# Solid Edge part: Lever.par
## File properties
Author: wojci
Template: ISO Metric Part.par
Last saved by: wojci
Revision: 29
Application: Solid Edge
Username: wojci
Accuracy: 0.990
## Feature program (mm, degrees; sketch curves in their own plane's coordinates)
sketch for "unnamed Protrusion 1" plane through (0, 0, 0) normal (0, -1, 0) x-axis (1, 0, 0)
  arc centre (32.0198, -7.9834) radius 5 from (27.2135, -9.3616) to (30.8101, -12.8349) ccw
  arc centre (32.3827, -6.5278) radius 6.5002 from (30.8101, -12.8349) to (34.1079, -0.2607) ccw
  line (10.286, 6.1805) -> (34.1079, -0.2607)
  line (-35.9088, 21.3204) -> (2.9031, 11.6435)
  arc centre (-37.1184, 16.4689) radius 5 from (-35.9088, 21.3204) to (-41.9699, 17.6786) ccw
  line (-47.5341, -4.6382) -> (-41.9699, 17.6786)
  line (-47.5341, -4.6382) -> (-31.6385, 4.1728)
  line (-30.2825, 9.6115) -> (-31.6385, 4.1728)
  line (-30.2825, 9.6115) -> (-6.0251, 3.5635)
  line (-1.6935, -6.7921) -> (27.2135, -9.3616)
extrude "unnamed Protrusion 1" add finite 27.5 along -normal
sketch for "ExtrudedCutout_1" plane through (-2.2401, 27.5, 3.5583) normal (0, 1, 0) x-axis (-0.996073, 0, 0.088541)
extrude "ExtrudedCutout_1" cut finite 8 along -normal
sketch for "unnamed Cutout 1" plane through (32.0198, 0, -7.9834) normal (0.241922, 0, 0.970296) x-axis (0.970296, 0, -0.241922)
  line (-7.5, 12.7) -> (-7.5, 5.4)
  line (7.5, 5.4) -> (-7.5, 5.4)
  line (7.5, 5.4) -> (7.5, 12.7)
  line (7.5, 12.7) -> (-7.5, 12.7)
extrude "unnamed Cutout 1" cut through along +normal
sketch for "ExtrudedProtrusion_3" plane through (-2.2401, 0, 3.5583) normal (0, -1, 0) x-axis (0.996073, 0, -0.088541)
  circle centre (2.5464, -3.346) radius 12
extrude "ExtrudedProtrusion_3" add finite 12.5 along -normal
sketch for "ExtrudedCutout_4" plane through (-2.2401, 0, 3.5583) normal (0, -1, 0) x-axis (0.970296, 0, -0.241922)
  line (4.0847, -14.8646) -> (-41.9656, -18.9106)
  line (-41.9656, -18.9106) -> (-41.9656, 9.0894)
  line (-41.9656, 9.0894) -> (3.0344, 9.0894)
  arc centre (3.0344, -2.9106) radius 12 from (3.0344, 9.0894) to (4.0847, -14.8646) ccw
extrude "ExtrudedCutout_4" cut finite 12.5 along -normal
sketch for "ExtrudedCutout_5" plane through (12.5099, 0, -0.3117) normal (0, -1, 0) x-axis (0.996073, 0, -0.088541)
  line (-2.79, 6.2698) -> (-2.79, -7.8641)
  arc centre (-12.4883, -0.7971) radius 12 from (-2.79, 6.2698) to (-2.79, -7.8641) ccw
extrude "ExtrudedCutout_5" cut finite 2.5 along -normal
sketch for "ExtrudedCutout_6" plane through (-14.7469, 27.5, 5.718) normal (0, 1, 0) x-axis (-0.970296, 0, 0.241922)
  line (-14.1589, -1.5234) -> (-8.984, 0.0195)
  arc centre (-15.6922, -1.9805) radius 7 from (-8.984, 0.0195) to (-15.6922, -8.9805) cw
  line (-15.6922, -3.5805) -> (-15.6922, -8.9805)
  dimension (linear) = 14.1589
  dimension (linear) = 15.6922
extrude "ExtrudedCutout_6" cut finite 15 along -normal
sketch for "ExtrudedProtrusion_4" plane through (-14.75, 27.5, 5.7186) normal (0, 1, 0) x-axis (-0.970296, 0, 0.241922)
  arc centre (-15.6953, -1.9804) radius 12 from (-15.6953, 10.0196) to (-26.4561, -7.2914) ccw
  arc centre (-15.6953, -1.9804) radius 12 from (-26.4561, -7.2914) to (-3.8632, 0.0196) ccw
  arc centre (-15.6953, -1.9804) radius 12 from (-15.6953, 10.0196) to (-3.8632, 0.0196) cw
extrude "ExtrudedProtrusion_4" add finite 25 along +normal
sketch for "ExtrudedCutout_7" plane through (-1.8397, 27.5, -3.5559) normal (0, -1, 0) x-axis (0.996073, 0, -0.088541)
  line (-9.8613, 7.5154) -> (-4.7993, 6.7209)
  line (-4.7993, 6.7209) -> (0.0738, 4.3942)
  arc centre (1.5177, 3.7049) radius 1.6 from (1.2696, 2.1242) to (0.0738, 4.3942) ccw
  line (1.2696, 2.1242) -> (0.4322, -3.2105)
  line (0.4322, -3.2105) -> (11.3247, -3.2105)
  arc centre (1.5177, 3.7049) radius 12 from (-9.8613, 7.5154) to (11.3247, -3.2105) ccw
extrude "ExtrudedCutout_7" cut finite 1 along -normal  FiniteDepth2 = 17 mm
sketch for "Hole_3" plane through (0, 52.5, 0) normal (0, 1, 0) x-axis (-1, 0, 0)
  hole centre (0, 0) bore radius 1.7
hole "Hole_3" diameter 3.4 through
chamfer "Chamfer_4" setback 3
chamfer "Chamfer_6" setback 1.5
chamfer "Chamfer_7" setback 2
sketch for "Hole_4" plane through (24.6721, 0, -5.1821) normal (0, -1, 0) x-axis (0.996073, 0, -0.088541)
  hole centre (7.5668, -2.1397) bore radius 1.2295
hole "Hole_4" nominal diameter 3 through  ThreadDepth = 2 mm
fillet "Round_8" radius 3.5
fillet "Round_9" radius 10
chamfer "Chamfer_11" setback 2
chamfer "Chamfer_12" setback 3.5643
fillet "Round_10" radius 1
chamfer "Chamfer_13" setback 1.5
fillet "Round_11" radius 1.5
sketch for "unnamed Cutout 2" plane through (-21.52, 12.5, 11.0446) normal (0, -1, 0) x-axis (0.970296, 0, -0.241922)
  line (-19.4473, -19.6454) -> (-19.4473, -2.5104)
  arc centre (-10.4473, -2.5104) radius 9 from (-19.4473, -2.5104) to (-10.4473, 6.4896) cw
  line (-10.4473, 6.4896) -> (-21.4473, 6.4896)
  line (-21.4473, -21.5104) -> (-21.4473, 6.4896)
  line (-19.4473, -19.6454) -> (-21.4473, -21.5104)
extrude "unnamed Cutout 2" cut through along -normal
fillet "Round_15" radius 3.5
fillet "Round_16" radius 3
fillet "Round_17" radius 1.5
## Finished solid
Body 1: solid body, 52 faces, 142 edges, 88 vertices.
  Faces by surface: plane 25, cylinder 20, cone 5, torus 2
  Edges by curve: line 72, circle 52, intersection 17, ellipse 1
Bounding box of the edges (mm; curved faces can reach further): 82.182 x 52.500 x 33.164, from (-43.2989, 0, -13.028) to (38.8829, 52.5, 20.1362).
Cylindrical faces by radius (mm): R1 x3, R1.2295 x3, R1.5 x3, R1.7 x1, R3 x1, R3.5 x2, R5 x2, R6.5002 x2, R9 x1, R10 x1, R12 x1
Conical faces (half-angle, radius in mm at the cone's reference point): 45 deg R10 x1, 45 deg R10.5 x1, 45 deg R12 x2, 45 deg R15 x1
Toroidal faces (ring radius, tube radius in mm): R2.7 r1 x2
Planar faces by outward normal: +y 5, -y 5, oblique 15
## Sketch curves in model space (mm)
line (32.0198, 0, -7.9834) -> (32.0198, 19.5, -7.9834)
line (39.297, 12.7, -9.7978) -> (24.7425, 12.7, -6.169)
line (24.7425, 12.7, -6.169) -> (24.7425, 5.4, -6.169)
line (39.297, 5.4, -9.7978) -> (24.7425, 5.4, -6.169)
line (39.297, 5.4, -9.7978) -> (39.297, 12.7, -9.7978)
line (2.9031, 0, 11.6435) -> (0, 0, 0)
line (-43.6633, 0, 10.8865) -> (-47.5341, 0, -4.6382)
line (-36.8712, 0, 9.193) -> (-43.6633, 0, 10.8865)
line (32.0198, 0, -7.9834) -> (30.8101, 0, -12.8349)
line (0, 0, 0) -> (-1.6935, 0, -6.7921)
line (0, 0, 0) -> (10.286, 0, 6.1805)
line (32.0198, 0, -7.9834) -> (27.2135, 0, -9.3616)
line (0, 0, 0) -> (-36.8712, 0, 9.193)
line (0, 0, 0) -> (32.0198, 0, -7.9834)
line (0, 0, 0) -> (-35, 0, 0)
line (-35.9921, 0, 1.7595) -> (-47.5341, 0, -4.6382)
circle centre (32.0198, 0, -7.9834) radius 8
arc centre (0, 0, 0) radius 7 from (-1.6935, 0, -6.7921) through (-6.4578, 0, -2.7013) to (-6.0251, 0, 3.5635)
line (-1.6935, 0, -6.7921) -> (27.2135, 0, -9.3616)
arc centre (32.0198, 0, -7.9834) radius 5 from (27.2135, 0, -9.3616) through (28.5465, 0, -11.5801) to (30.8101, 0, -12.8349)
arc centre (32.3827, 0, -6.5278) radius 6.5002 from (30.8101, 0, -12.8349) through (38.7577, 0, -7.7971) to (34.1079, 0, -0.2607)
line (10.286, 0, 6.1805) -> (34.1079, 0, -0.2607)
arc centre (0, 0, 0) radius 12 from (2.9031, 0, 11.6435) through (7.1379, 0, 9.6463) to (10.286, 0, 6.1805)
line (-35.9088, 0, 21.3204) -> (2.9031, 0, 11.6435)
arc centre (-37.1184, 0, 16.4689) radius 5 from (-35.9088, 0, 21.3204) through (-39.8171, 0, 20.6781) to (-41.9699, 0, 17.6786)
line (-47.5341, 0, -4.6382) -> (-41.9699, 0, 17.6786)
line (-47.5341, 0, -4.6382) -> (-31.6385, 0, 4.1728)
line (-30.2825, 0, 9.6115) -> (-31.6385, 0, 4.1728)
line (-30.2825, 0, 9.6115) -> (-6.0251, 0, 3.5635)
line (-31.3956, 0, 20.1952) -> (-35.9921, 0, 1.7595)
circle centre (32.0198, 0, -7.9834) radius 5
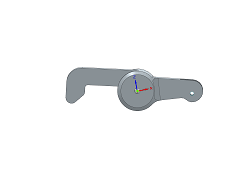
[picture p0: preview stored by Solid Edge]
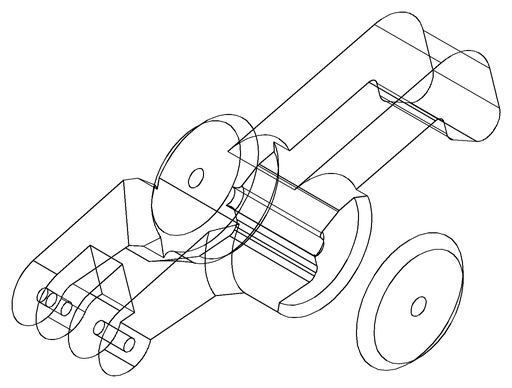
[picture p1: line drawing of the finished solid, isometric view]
